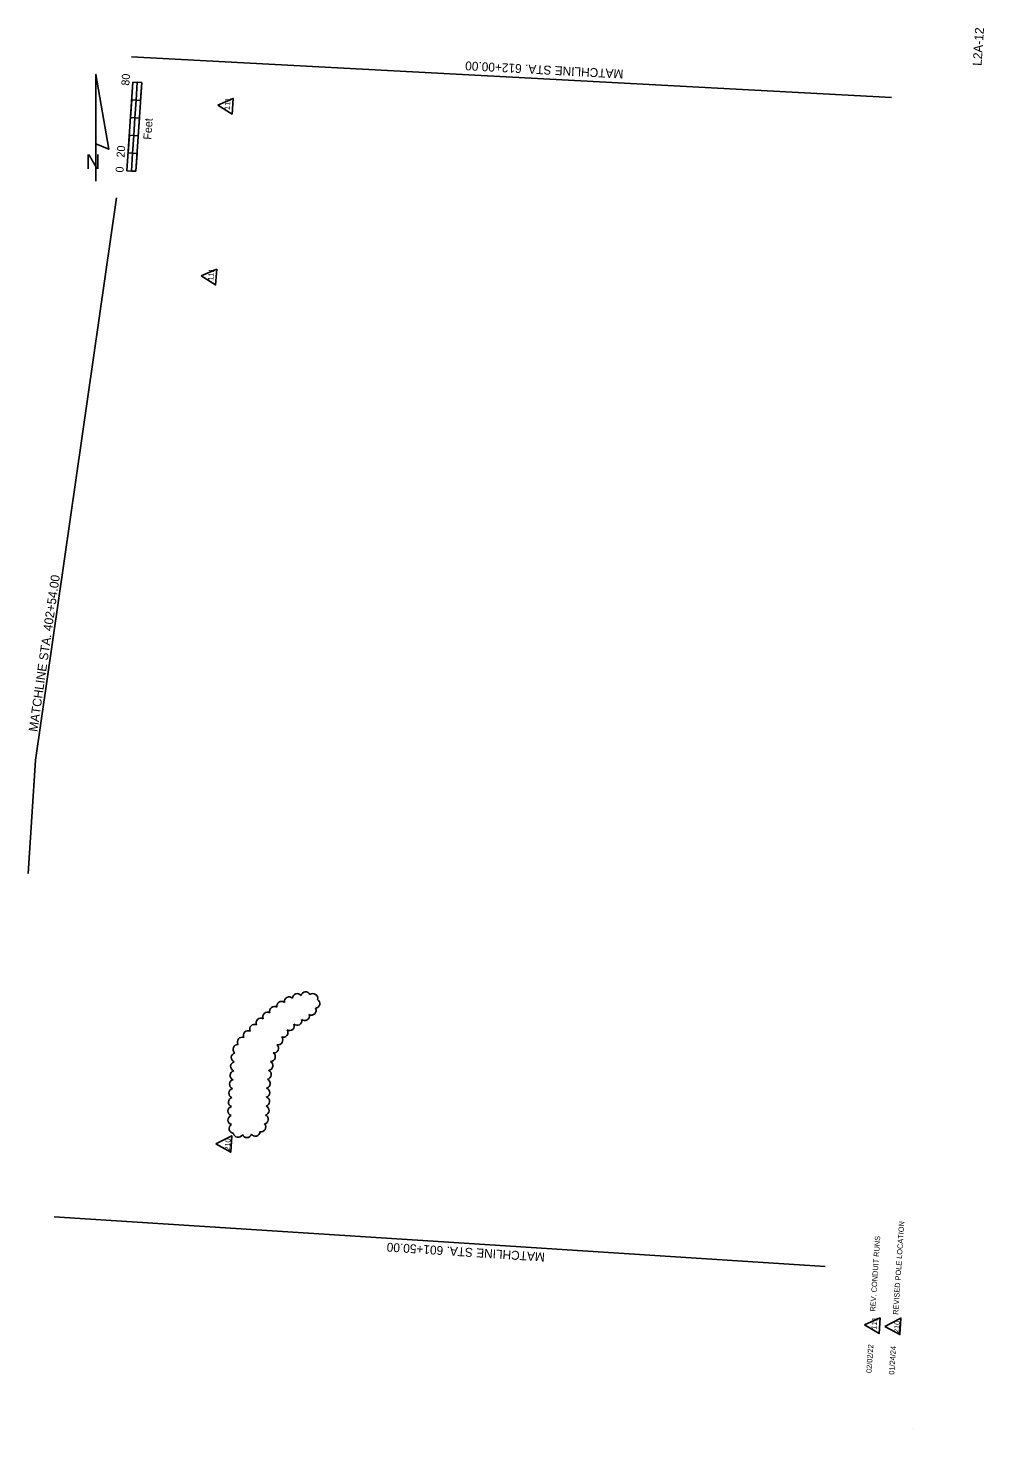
# Model space of a CAD drawing. Extents: x 928614 to 929474, y 635831 to 637091.
import ezdxf

# ---------------------------------------------------------------- set-up
doc = ezdxf.new("R2010")
doc.units = 0
for name, color, linetype in [('AdhocPoint_dp', 7, 'Continuous'), ('Cloud_dp', 7, 'Continuous'), ('MatchLines_dp', 7, 'Continuous'), ('NorthArw_dp', 7, 'Continuous'), ('Scale_dp', 7, 'Continuous'), ('TextShtNo', 7, 'Continuous')]:
    doc.layers.add(name, color=color, linetype=linetype)

msp = doc.modelspace()

# ---------------------------------------------------------------- linework, layer by layer
at = {"layer": 'AdhocPoint_dp'}
msp.add_line((929410.4, 635830.6), (929410.4, 635830.6), dxfattribs=at)
at = {"layer": 'Cloud_dp'}
for points in [[(928784.7, 637021.6), (928797.7, 637013.7), (928798.7, 637027.7)], [(928769.9, 636868), (928782.9, 636860), (928783.9, 636874.1)], [(928783, 636087), (928796.4, 636079.5), (928797.3, 636094.4)], [(929366.3, 635924.4), (929379.4, 635916.4), (929380.3, 635930.5)], [(929384.7, 635922.9), (929398.1, 635915.5), (929399.1, 635930.4)]]:
    msp.add_lwpolyline(points, close=True, dxfattribs=at)
for centre, radius, start, end in [((928848.9, 636215.1), 4.23, 44.2655, 189.2655), ((928856.2, 636218.1), 4.23, 35.6453, 180.6453), ((928863.8, 636219.7), 4.23, 23.6216, 168.6216), ((928870.4, 636218.1), 4.23, 344.0108, 129.0108), ((928872.3, 636213.3), 4.23, 275.4691, 60.4691), ((928829.5, 636201.4), 4.23, 59.0346, 204.0346), ((928835.6, 636206.5), 4.23, 55.478, 200.478), ((928842.1, 636211.1), 4.23, 50.7499, 195.7499), ((928862.9, 636202.3), 4.23, 230.9717, 15.9717), ((928869, 636207.2), 4.23, 241.7092, 26.7092), ((928817.7, 636190.4), 4.23, 61.663, 206.663), ((928823.5, 636196), 4.23, 60.6312, 205.6312), ((928849.4, 636193.2), 4.23, 238.7935, 23.7935), ((928856.1, 636198), 4.23, 227.7962, 12.7962), ((928806.7, 636178.8), 4.23, 67.8058, 212.8058), ((928812, 636184.7), 4.23, 63.5769, 208.5769), ((928839, 636180.4), 4.23, 256.8541, 41.8541), ((928843.7, 636187.2), 4.23, 249.1655, 34.1655), ((928801.2, 636164.8), 4.23, 103.6961, 248.6961), ((928802.8, 636172.2), 4.23, 85.8374, 230.8374), ((928832.3, 636165.5), 4.23, 269.8398, 54.8398), ((928835.2, 636173.1), 4.23, 263.2828, 48.2828), ((928800.1, 636148.7), 4.23, 103.6961, 248.6961), ((928800.6, 636156.8), 4.23, 103.6961, 248.6961), ((928828.7, 636149.5), 4.23, 279.3925, 64.3925), ((928830.2, 636157.6), 4.23, 275.1353, 60.1353), ((928799.6, 636140.7), 4.23, 103.6961, 248.6961), ((928827.8, 636141.4), 4.23, 282.8593, 67.8593), ((928798.6, 636124.6), 4.23, 104.5077, 249.5077), ((928799, 636132.6), 4.23, 103.7449, 248.7449), ((928827.1, 636125.2), 4.23, 285.5466, 70.5466), ((928827.3, 636133.3), 4.23, 285.593, 70.593), ((928798.2, 636116.5), 4.23, 105.956, 250.956), ((928826.7, 636117.2), 4.23, 284.046, 69.046), ((928798.2, 636108.5), 4.23, 108.7541, 253.7541), ((928799.2, 636100.8), 4.24, 121.1025, 266.1025), ((928823.7, 636102.2), 4.23, 257.4624, 42.4624), ((928826, 636109.2), 4.23, 280.7407, 65.7407), ((928803.1, 636097.2), 4.23, 188.6667, 333.6667), ((928810.9, 636096.9), 4.23, 200.8289, 345.8289), ((928818.5, 636098.2), 4.23, 213.6368, 358.6368)]:
    msp.add_arc(centre, radius, start, end, dxfattribs=at)
at = {"layer": 'MatchLines_dp'}
for p, q in [((928621, 636432.3), (928693.8, 636938.4)), ((928614.2, 636330.3), (928621, 636432.3))]:
    msp.add_line(p, q, dxfattribs=at)
for points in [[(929390.5, 637028.7), (929066.7, 637046), (928707.2, 637065.2)], [(929330.9, 635976.8), (928997, 635998.3), (928637.8, 636021.5)]]:
    msp.add_lwpolyline(points, dxfattribs=at)
at = {"layer": 'NorthArw_dp'}
msp.add_line((928675.2, 636953.3), (928675.2, 637049.3), dxfattribs=at)
msp.add_lwpolyline([(928675.2, 636986.9), (928675.2, 637049.3), (928686.8, 636982.1)], close=True, dxfattribs=at)
at = {"layer": 'Scale_dp'}
for p, q in [((928708.5, 637042.5), (928703.1, 636962.7)), ((928716.4, 637042), (928708.5, 637042.5)), ((928711.1, 636962.2), (928716.4, 637042)), ((928703.1, 636962.7), (928711.1, 636962.2))]:
    msp.add_line(p, q, dxfattribs=at)
for points in [[(928715.4, 637026), (928711.4, 637026.3), (928712.4, 637042.3), (928716.4, 637042)], [(928710.3, 637010.3), (928706.3, 637010.6), (928707.4, 637026.6), (928711.4, 637026.3)], [(928713.3, 636994.1), (928709.3, 636994.4), (928710.3, 637010.3), (928714.3, 637010.1)], [(928708.2, 636978.4), (928704.2, 636978.7), (928705.3, 636994.6), (928709.3, 636994.4)], [(928711.1, 636962.2), (928707.1, 636962.4), (928708.2, 636978.4), (928712.2, 636978.1)]]:
    msp.add_lwpolyline(points, close=True, dxfattribs=at)

# ---------------------------------------------------------------- texts
at = {"layer": 'Cloud_dp'}
for s, p in [('111', (928795.6, 637017.2)), ('111', (928780.8, 636863.6)), ('210', (928795.7, 636080.8)), ('REVISED POLE LOCATION', (929396.6, 635933.2)), ('REV. CONDUIT RUNS', (929376, 635936.1)), ('111', (929377.2, 635920)), ('210', (929397.4, 635916.7)), ('02/02/22', (929372.6, 635880.8)), ('01/24/24', (929393, 635879.3))]:
    msp.add_text(s, height=4.8, rotation=86.1961, dxfattribs=at).set_placement(p)
at = {"layer": 'MatchLines_dp'}
for s, rotation, p in [('MATCHLINE STA. 612+00.00', 176.9478, (929149.7, 637053.6)), ('MATCHLINE STA. 402+54.00', 81.813, (928622.6, 636457.5)), ('MATCHLINE STA. 601+50.00', 176.3155, (929079.1, 635989.1))]:
    msp.add_text(s, height=8, rotation=rotation, dxfattribs=at).set_placement(p)
at = {"layer": 'NorthArw_dp'}
msp.add_text('N', height=13.4, dxfattribs=at).set_placement((928666.1, 636964.2))
at = {"layer": 'Scale_dp'}
for s, p in [('80', (928705.2, 637039.1)), ('Feet', (928725, 636990.5)), ('20', (928700.9, 636974.4)), ('0', (928700, 636960.9))]:
    msp.add_text(s, height=7.2, rotation=86.1961, dxfattribs=at).set_placement(p)
at = {"layer": 'TextShtNo'}
msp.add_text('L2A-12', height=8, rotation=86.1961, dxfattribs=at).set_placement((929471.5, 637056.9))

doc.saveas('drawing.dxf')
